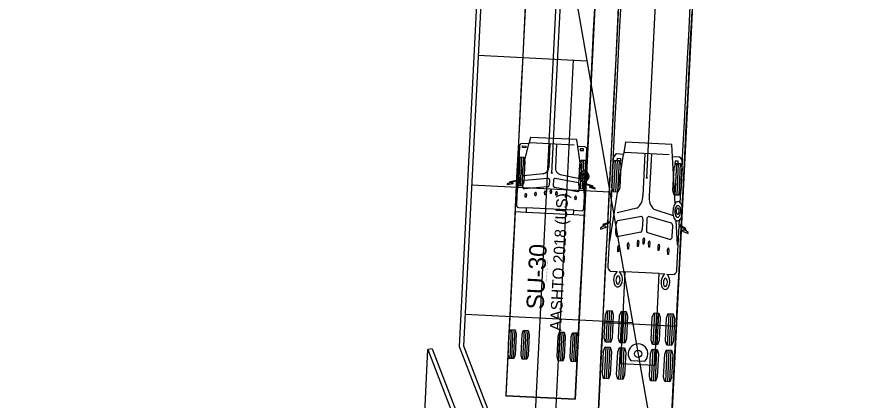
# Model space of a CAD drawing. Extents: x 260275 to 261282, y 610916 to 614143.
# Drawn here: x 260986.2 to 261084.3, y 612110.7 to 612155 of the extents above; entities that cross this region are included whole.
import ezdxf

# ---------------------------------------------------------------- set-up
doc = ezdxf.new("R2010")
doc.units = 0
for name, color, linetype in [('GE_X_Alignment', 7, 'Continuous'), ('PV_P_Curb', 7, 'Continuous'), ('PV_P_EOP', 7, 'Continuous'), ('PV_P_Joint', 7, 'Continuous'), ('TopoDOT_Transients', 7, 'Continuous')]:
    doc.layers.add(name, color=color, linetype=linetype)

msp = doc.modelspace()

# ---------------------------------------------------------------- linework, layer by layer
at = {"layer": 'GE_X_Alignment'}
msp.add_line((260986.249, 610915.954), (261148.276, 614142.838), dxfattribs=at)
at = {"layer": 'PV_P_Curb'}
for p, q in [((261041.82, 612206.041), (261037.345, 612116.921)), ((261034.244, 612116.627), (261033.739, 612116.547)), ((261034.244, 612116.627), (261053.627, 612066.228)), ((261037.345, 612116.921), (261056.48, 612067.167)), ((261034.545, 612115.844), (261053.68, 612066.09))]:
    msp.add_line(p, q, dxfattribs=at)
at = {"layer": 'PV_P_EOP'}
for p, q in [((261042.321, 612206.054), (261037.849, 612116.977)), ((261045.432, 612188.236), (261059.122, 612109.815)), ((261031.212, 612066.209), (261033.739, 612116.547)), ((261033.739, 612116.547), (261053.122, 612066.147)), ((261037.86, 612116.976), (261056.985, 612067.248))]:
    msp.add_line(p, q, dxfattribs=at)
at = {"layer": 'PV_P_Joint'}
for p, q in [((261039.537, 612150.6), (261052.112, 612149.968)), ((261050.523, 612150.048), (261048.266, 612105.105)), ((261038.785, 612135.619), (261054.757, 612134.817)), ((261038.033, 612120.638), (261057.406, 612119.665))]:
    msp.add_line(p, q, dxfattribs=at)
at = {"layer": 'TopoDOT_Transients'}
for p, q in [((261059.045, 612136.423), (261081.046, 612574.591)), ((261048.059, 612136.974), (261068.197, 612538.052)), ((261044.048, 612134.867), (261045.389, 612140.334)), ((261044.677, 612139.913), (261044.687, 612140.107)), ((261044.687, 612140.107), (261045.065, 612140.088)), ((261045.065, 612140.088), (261045.056, 612139.895)), ((261050.643, 612140.193), (261045.544, 612140.449)), ((261047.844, 612140.334), (261047.71, 612137.669)), ((261048.609, 612140.295), (261048.475, 612137.631)), ((261051.47, 612137.084), (261051.052, 612140.05)), ((261061.928, 612140.283), (261056.563, 612140.552)), ((261045.056, 612139.895), (261044.677, 612139.913)), ((261051.349, 612139.773), (261051.339, 612139.579)), ((261051.339, 612139.579), (261051.718, 612139.56)), ((261051.727, 612139.754), (261051.349, 612139.773)), ((261051.718, 612139.56), (261051.727, 612139.754)), ((261051.974, 612137.175), (261052.1, 612139.694)), ((261054.771, 612129.067), (261056.342, 612139.135)), ((261061.602, 612139.096), (261056.503, 612139.352)), ((261058.803, 612139.237), (261058.558, 612134.351)), ((261059.568, 612139.198), (261059.322, 612134.313)), ((261044.355, 612138.829), (261044.188, 612135.5)), ((261044.563, 612138.818), (261044.396, 612135.489)), ((261044.772, 612138.808), (261044.604, 612135.479)), ((261051.513, 612138.469), (261051.346, 612135.14)), ((261051.721, 612138.459), (261051.554, 612135.13)), ((261051.929, 612138.449), (261051.762, 612135.119)), ((261055.371, 612138.443), (261055.187, 612134.781)), ((261055.6, 612138.431), (261055.416, 612134.769)), ((261055.612, 612138.335), (261055.63, 612138.69)), ((261055.99, 612138.316), (261055.612, 612138.335)), ((261055.63, 612138.69), (261056.008, 612138.671)), ((261055.829, 612138.42), (261055.645, 612134.758)), ((261056.008, 612138.671), (261055.99, 612138.316)), ((261062.301, 612133.437), (261062.006, 612138.851)), ((261062.445, 612138.087), (261062.261, 612134.425)), ((261062.292, 612138.356), (261062.274, 612138)), ((261062.67, 612138.337), (261062.292, 612138.356)), ((261062.674, 612138.076), (261062.49, 612134.414)), ((261062.652, 612137.981), (261062.67, 612138.337)), ((261062.903, 612138.064), (261062.719, 612134.402)), ((261062.905, 612133.54), (261063.141, 612138.235)), ((261062.274, 612138), (261062.652, 612137.981)), ((261047.072, 612136.893), (261044.794, 612136.662)), ((261044.9, 612136.163), (261047.609, 612136.379)), ((261047.78, 612136.168), (261047.749, 612135.552)), ((261048.255, 612136.144), (261048.224, 612135.528)), ((261051.12, 612135.851), (261048.447, 612136.337)), ((261049.032, 612136.795), (261051.288, 612136.334)), ((261044.708, 612135.353), (261044.739, 612135.969)), ((261047.588, 612135.358), (261044.879, 612135.142)), ((261048.366, 612135.319), (261051.039, 612134.833)), ((261051.23, 612135.025), (261051.261, 612135.641)), ((261051.838, 612134.475), (261051.622, 612136.009)), ((261044.991, 612134.183), (261044.97, 612134.484)), ((261045.073, 612134.178), (261044.991, 612134.183)), ((261045.124, 612134.476), (261045.073, 612134.178)), ((261046.117, 612134.337), (261046.096, 612134.652)), ((261046.2, 612134.333), (261046.117, 612134.337)), ((261046.251, 612134.644), (261046.2, 612134.333)), ((261047.242, 612134.463), (261047.221, 612134.764)), ((261047.325, 612134.459), (261047.242, 612134.463)), ((261047.376, 612134.756), (261047.325, 612134.459)), ((261047.898, 612134.598), (261047.877, 612134.9)), ((261047.981, 612134.594), (261047.898, 612134.598)), ((261048.031, 612134.892), (261047.981, 612134.594)), ((261048.537, 612134.398), (261048.516, 612134.699)), ((261048.62, 612134.394), (261048.537, 612134.398)), ((261048.67, 612134.691), (261048.62, 612134.394)), ((261049.644, 612134.16), (261049.623, 612134.461)), ((261049.726, 612134.155), (261049.644, 612134.16)), ((261049.777, 612134.453), (261049.726, 612134.155)), ((261050.749, 612133.893), (261050.728, 612134.195)), ((261050.882, 612134.187), (261050.831, 612133.889)), ((261050.831, 612133.889), (261050.749, 612133.893)), ((261050.565, 612132.129), (261045.08, 612132.404)), ((261050.592, 612132.66), (261045.107, 612132.935)), ((261057.886, 612132.904), (261055.593, 612132.385)), ((261059.846, 612132.805), (261062.087, 612132.056)), ((261055.679, 612131.476), (261058.402, 612131.985)), ((261058.565, 612131.606), (261058.508, 612130.477)), ((261059.04, 612131.582), (261058.983, 612130.453)), ((261061.899, 612131.164), (261059.24, 612131.943)), ((261062.561, 612128.675), (261062.408, 612131.475)), ((261053.998, 612130.835), (261053.977, 612130.819)), ((261054.024, 612130.832), (261053.998, 612130.835)), ((261055.452, 612129.985), (261055.509, 612131.114)), ((261061.975, 612129.657), (261062.031, 612130.786)), ((261063.48, 612130.357), (261063.506, 612130.357)), ((261063.506, 612130.357), (261063.526, 612130.339)), ((261058.338, 612130.114), (261055.615, 612129.606)), ((261058.618, 612128.736), (261058.609, 612129.287)), ((261058.764, 612129.279), (261058.7, 612128.732)), ((261059.116, 612130.075), (261061.775, 612129.297)), ((261055.687, 612127.853), (261055.679, 612128.404)), ((261055.833, 612128.396), (261055.769, 612127.849)), ((261056.822, 612128.183), (261056.814, 612128.758)), ((261056.968, 612128.751), (261056.905, 612128.178)), ((261057.955, 612128.46), (261057.946, 612129.011)), ((261058.037, 612128.456), (261057.955, 612128.46)), ((261058.101, 612129.003), (261058.037, 612128.456)), ((261058.7, 612128.732), (261058.618, 612128.736)), ((261059.25, 612128.395), (261059.241, 612128.946)), ((261059.332, 612128.391), (261059.25, 612128.395)), ((261059.395, 612128.938), (261059.332, 612128.391)), ((261060.349, 612128.006), (261060.34, 612128.556)), ((261060.494, 612128.548), (261060.431, 612128.001)), ((261055.769, 612127.849), (261055.687, 612127.853)), ((261056.905, 612128.178), (261056.822, 612128.183)), ((261060.431, 612128.001), (261060.349, 612128.006)), ((261061.445, 612127.564), (261061.437, 612128.115)), ((261061.527, 612127.56), (261061.445, 612127.564)), ((261061.591, 612128.107), (261061.527, 612127.56)), ((261054.848, 612125.619), (261055.622, 612125.581)), ((261060.478, 612125.337), (261056.509, 612125.536)), ((261061.364, 612125.292), (261062.139, 612125.253)), ((261054.498, 612121.065), (261054.314, 612117.402)), ((261054.727, 612121.053), (261054.543, 612117.391)), ((261054.956, 612121.042), (261054.772, 612117.379)), ((261056.146, 612120.982), (261055.962, 612117.32)), ((261056.375, 612120.97), (261056.191, 612117.308)), ((261056.604, 612120.959), (261056.42, 612117.297)), ((261059.925, 612120.792), (261059.741, 612117.13)), ((261060.154, 612120.781), (261059.97, 612117.119)), ((261060.382, 612120.769), (261060.199, 612117.107)), ((261061.573, 612120.709), (261061.389, 612117.047)), ((261061.801, 612120.698), (261061.618, 612117.036)), ((261062.03, 612120.686), (261061.846, 612117.024)), ((261043.352, 612118.854), (261043.185, 612115.525)), ((261043.561, 612118.844), (261043.393, 612115.514)), ((261043.769, 612118.833), (261043.601, 612115.504)), ((261044.851, 612118.779), (261044.683, 612115.45)), ((261045.059, 612118.768), (261044.891, 612115.439)), ((261045.267, 612118.758), (261045.1, 612115.429)), ((261049.012, 612118.57), (261048.845, 612115.241)), ((261049.22, 612118.559), (261049.053, 612115.23)), ((261049.428, 612118.549), (261049.261, 612115.22)), ((261050.51, 612118.495), (261050.343, 612115.165)), ((261050.718, 612118.484), (261050.551, 612115.155)), ((261050.926, 612118.474), (261050.759, 612115.145)), ((261054.288, 612116.87), (261054.104, 612113.208)), ((261054.516, 612116.858), (261054.333, 612113.196)), ((261054.745, 612116.847), (261054.561, 612113.185)), ((261055.935, 612116.787), (261055.752, 612113.125)), ((261056.164, 612116.776), (261055.98, 612113.114)), ((261056.393, 612116.764), (261056.209, 612113.102)), ((261059.714, 612116.597), (261059.53, 612112.935)), ((261059.943, 612116.586), (261059.759, 612112.924)), ((261060.172, 612116.574), (261059.988, 612112.912)), ((261061.362, 612116.515), (261061.178, 612112.853)), ((261061.591, 612116.503), (261061.407, 612112.841)), ((261061.82, 612116.492), (261061.636, 612112.83)), ((261057.175, 612115.293), (261058.789, 612115.212))]:
    msp.add_line(p, q, dxfattribs=at)
for points in [[(261051.548, 612071.863), (261074.206, 612523.277)], [(261082.631, 612521.243), (261060.03, 612071.291)], [(261042.767, 612111.356), (261063.016, 612514.614)], [(261070.923, 612512.551), (261050.75, 612110.806), (261042.76, 612111.207), (261042.767, 612111.356), (261042.767, 612111.356)], [(261043.061, 612117.2), (261043.228, 612120.528), (261043.395, 612123.857), (261043.562, 612127.185), (261043.729, 612130.514), (261043.896, 612133.842), (261044.064, 612137.171), (261044.231, 612140.499), (261044.398, 612143.827), (261044.565, 612147.156), (261044.732, 612150.484), (261044.899, 612153.813), (261045.066, 612157.141)], [(261044.064, 612137.175), (261044.231, 612140.503), (261044.398, 612143.832), (261044.565, 612147.16), (261044.732, 612150.489), (261044.899, 612153.817), (261045.067, 612157.145)], [(261051.051, 612116.799), (261051.218, 612120.127), (261051.385, 612123.456), (261051.552, 612126.784), (261051.719, 612130.112), (261051.886, 612133.441), (261052.054, 612136.769), (261052.221, 612140.098), (261052.388, 612143.426), (261052.555, 612146.755), (261052.722, 612150.083), (261052.889, 612153.412), (261053.056, 612156.74)], [(261052.054, 612136.774), (261052.221, 612140.102), (261052.388, 612143.43), (261052.555, 612146.759), (261052.722, 612150.087), (261052.889, 612153.416), (261053.056, 612156.744)], [(261053.438, 612109.507), (261053.605, 612112.837), (261053.772, 612116.166), (261053.94, 612119.496), (261054.107, 612122.825), (261054.274, 612126.155), (261054.441, 612129.484), (261054.608, 612132.814), (261054.776, 612136.144), (261054.943, 612139.473), (261055.11, 612142.803), (261055.277, 612146.132), (261055.444, 612149.462), (261055.611, 612152.791), (261055.779, 612156.121)], [(261055.05, 612136.623), (261055.217, 612139.953), (261055.384, 612143.282), (261055.551, 612146.612), (261055.719, 612149.941), (261055.886, 612153.271), (261056.053, 612156.6)], [(261063.04, 612136.222), (261063.207, 612139.551), (261063.374, 612142.881), (261063.541, 612146.211), (261063.709, 612149.54), (261063.876, 612152.87), (261064.043, 612156.199)], [(261061.927, 612109.081), (261062.095, 612112.41), (261062.262, 612115.74), (261062.429, 612119.07), (261062.596, 612122.399), (261062.763, 612125.729), (261062.93, 612129.058), (261063.098, 612132.388), (261063.265, 612135.717), (261063.432, 612139.047), (261063.599, 612142.376), (261063.766, 612145.706), (261063.934, 612149.035), (261064.101, 612152.365), (261064.268, 612155.695)], [(261051.862, 612140.009), (261051.056, 612140.05), (261051.051, 612140.054), (261050.942, 612140.832), (261050.9, 612140.837), (261048.259, 612140.969), (261045.619, 612141.102), (261045.577, 612141.102), (261045.39, 612140.339), (261045.385, 612140.334), (261044.578, 612140.375)], [(261044.31, 612140.085), (261044.113, 612136.157), (261044.105, 612136.145), (261043.264, 612135.961), (261043.263, 612135.961)], [(261061.928, 612140.283), (261056.563, 612140.552), (261056.342, 612139.135), (261055.529, 612139.176)], [(261062.819, 612138.81), (261062.006, 612138.851), (261061.928, 612140.271)], [(261055.151, 612138.636), (261054.786, 612131.369), (261054.03, 612131.037)], [(261043.219, 612135.89), (261043.216, 612135.843), (261043.215, 612135.842), (261042.914, 612135.726), (261042.911, 612135.661), (261042.914, 612135.661), (261043.576, 612135.767), (261043.579, 612135.768), (261043.582, 612135.824), (261043.579, 612135.824), (261043.263, 612135.848), (261043.262, 612135.849), (261043.265, 612135.893)], [(261043.277, 612135.913), (261043.278, 612135.913), (261044.105, 612136.091), (261044.109, 612136.079), (261043.97, 612133.308)], [(261051.76, 612132.917), (261051.899, 612135.688), (261051.904, 612135.699), (261052.71, 612135.439), (261052.71, 612135.439)], [(261052.729, 612135.486), (261052.728, 612135.486), (261051.909, 612135.753), (261051.903, 612135.766), (261051.914, 612135.993)], [(261052.72, 612135.418), (261052.718, 612135.374), (261052.718, 612135.374), (261052.401, 612135.381), (261052.398, 612135.381), (261052.395, 612135.325), (261052.398, 612135.324), (261053.046, 612135.152), (261053.049, 612135.152), (261053.052, 612135.217), (261052.764, 612135.363), (261052.764, 612135.363), (261052.766, 612135.411)], [(261044.208, 612132.98), (261045.103, 612132.935), (261045.106, 612132.932), (261045.08, 612132.405), (261045.069, 612132.405), (261043.827, 612132.467), (261042.76, 612111.207), (261046.755, 612111.007), (261050.75, 612110.806), (261051.817, 612132.066), (261050.576, 612132.128), (261050.565, 612132.13), (261050.591, 612132.656), (261050.595, 612132.66), (261051.49, 612132.615)], [(261054.042, 612130.95), (261054.042, 612130.95), (261054.781, 612131.269), (261054.526, 612126.194)], [(261063.496, 612130.562), (261062.776, 612130.967), (261062.805, 612131.54)], [(261053.982, 612130.906), (261053.977, 612130.819), (261053.67, 612130.593), (261053.664, 612130.473), (261054.338, 612130.697), (261054.343, 612130.8), (261054.024, 612130.832), (261054.029, 612130.914)], [(261062.516, 612125.793), (261062.771, 612130.868), (261063.474, 612130.477), (261063.475, 612130.476)], [(261063.484, 612130.439), (261063.48, 612130.357), (261063.16, 612130.357), (261063.154, 612130.254), (261063.802, 612129.964), (261063.809, 612130.084), (261063.526, 612130.339), (261063.53, 612130.427)], [(261055.879, 612125.568), (261056.509, 612125.536), (261055.977, 612114.949), (261059.946, 612114.75), (261060.478, 612125.337), (261061.107, 612125.305)], [(261060.011, 612071.363), (261060.033, 612071.362), (261062.437, 612119.231), (261058.192, 612119.444), (261053.948, 612119.657), (261051.544, 612071.788), (261051.567, 612071.787)]]:
    msp.add_lwpolyline(points, dxfattribs=at)
for points in [[(261044.304, 612138.831), (261044.823, 612138.805), (261044.956, 612138.331), (261044.836, 612135.934), (261044.656, 612135.476), (261044.137, 612135.502), (261044.004, 612135.976), (261044.124, 612138.373)], [(261051.461, 612138.472), (261051.981, 612138.446), (261052.114, 612137.972), (261051.994, 612135.575), (261051.814, 612135.117), (261051.294, 612135.143), (261051.161, 612135.617), (261051.282, 612138.014)], [(261055.314, 612138.445), (261055.885, 612138.417), (261056.032, 612137.895), (261055.899, 612135.259), (261055.701, 612134.755), (261055.13, 612134.783), (261054.984, 612135.305), (261055.116, 612137.941)], [(261062.388, 612138.09), (261062.96, 612138.062), (261063.106, 612137.54), (261062.974, 612134.904), (261062.776, 612134.4), (261062.205, 612134.428), (261062.058, 612134.95), (261062.191, 612137.586)], [(261054.441, 612121.067), (261055.013, 612121.039), (261055.159, 612120.517), (261055.027, 612117.881), (261054.829, 612117.377), (261054.258, 612117.405), (261054.111, 612117.927), (261054.244, 612120.563)], [(261056.089, 612120.985), (261056.661, 612120.956), (261056.807, 612120.435), (261056.675, 612117.798), (261056.477, 612117.294), (261055.905, 612117.323), (261055.759, 612117.844), (261055.891, 612120.481)], [(261059.868, 612120.795), (261060.439, 612120.766), (261060.586, 612120.245), (261060.453, 612117.608), (261060.255, 612117.104), (261059.684, 612117.133), (261059.538, 612117.654), (261059.67, 612120.291)], [(261061.516, 612120.712), (261062.087, 612120.683), (261062.233, 612120.162), (261062.101, 612117.525), (261061.903, 612117.021), (261061.332, 612117.05), (261061.186, 612117.571), (261061.318, 612120.208)], [(261043.301, 612118.857), (261043.82, 612118.831), (261043.953, 612118.357), (261043.833, 612115.96), (261043.653, 612115.501), (261043.134, 612115.527), (261043.001, 612116.001), (261043.121, 612118.398)], [(261044.799, 612118.781), (261045.318, 612118.755), (261045.451, 612118.281), (261045.331, 612115.884), (261045.151, 612115.426), (261044.632, 612115.452), (261044.499, 612115.926), (261044.619, 612118.323)], [(261048.96, 612118.572), (261049.48, 612118.546), (261049.613, 612118.072), (261049.492, 612115.675), (261049.313, 612115.217), (261048.793, 612115.243), (261048.66, 612115.717), (261048.781, 612118.114)], [(261050.459, 612118.497), (261050.978, 612118.471), (261051.111, 612117.997), (261050.991, 612115.6), (261050.811, 612115.142), (261050.291, 612115.168), (261050.158, 612115.642), (261050.279, 612118.039)], [(261054.231, 612116.873), (261054.802, 612116.844), (261054.948, 612116.323), (261054.816, 612113.686), (261054.618, 612113.182), (261054.047, 612113.211), (261053.901, 612113.732), (261054.033, 612116.369)], [(261055.879, 612116.79), (261056.45, 612116.761), (261056.596, 612116.24), (261056.464, 612113.603), (261056.266, 612113.099), (261055.695, 612113.128), (261055.548, 612113.649), (261055.681, 612116.286)], [(261059.657, 612116.6), (261060.229, 612116.571), (261060.375, 612116.05), (261060.243, 612113.413), (261060.045, 612112.909), (261059.473, 612112.938), (261059.327, 612113.459), (261059.459, 612116.096)], [(261061.305, 612116.517), (261061.876, 612116.489), (261062.023, 612115.967), (261061.89, 612113.331), (261061.693, 612112.827), (261061.121, 612112.855), (261060.975, 612113.377), (261061.107, 612116.013)]]:
    msp.add_lwpolyline(points, close=True, dxfattribs=at)
for centre, radius in [((261044.064, 612137.175), 0.0417), ((261048.059, 612136.974), 0.0417), ((261051.799, 612136.591), 0.374), ((261051.799, 612136.591), 0.193), ((261052.054, 612136.774), 0.0417), ((261055.05, 612136.623), 0.0417), ((261059.045, 612136.423), 0.0417), ((261063.04, 612136.222), 0.0417), ((261043.061, 612117.2), 0.0417), ((261051.051, 612116.799), 0.0417), ((261058.022, 612116.06), 0.424)]:
    msp.add_circle(centre, radius, dxfattribs=at)
for centre, radius, start, end in [((261044.592, 612140.093), 0.282, 92.67391, 181.75333), ((261051.821, 612139.73), 0.282, 352.49767, 81.5771), ((261055.93, 612138.493), 0.792, 120.43659, 169.59206), ((261062.352, 612138.171), 0.792, 4.65895, 53.81442), ((261046.938, 612137.654), 0.773, 280.01597, 1.10013), ((261049.242, 612137.539), 0.773, 173.15088, 254.23504), ((261051.868, 612136.596), 0.629, 129.17109, 177.86038), ((261051.803, 612136.677), 0.526, 71.07067, 129.31667), ((261051.732, 612136.595), 0.628, 286.8788, 67.3705), ((261044.931, 612135.973), 0.193, 99.26792, 181.18241), ((261047.598, 612136.195), 0.184, 351.66723, 86.52737), ((261048.439, 612136.153), 0.184, 87.72364, 182.58377), ((261051.868, 612136.581), 0.63, 176.4803, 228.88311), ((261051.795, 612136.504), 0.524, 229.38452, 283.18459), ((261043.242, 612135.925), 0.0418, 59.61742, 236.63235), ((261043.236, 612135.925), 0.0434, 312.53921, 343.21198), ((261044.89, 612135.326), 0.184, 171.66167, 266.53293), ((261047.557, 612135.548), 0.193, 279.26299, 1.18734), ((261048.415, 612135.505), 0.193, 173.06366, 254.98801), ((261051.07, 612135.665), 0.193, 353.06859, 74.98308), ((261052.753, 612135.447), 0.0434, 191.03902, 221.7118), ((261052.747, 612135.448), 0.0418, 297.61865, 114.63358), ((261045.06, 612134.498), 0.091, 94.64508, 188.80895), ((261045.036, 612134.499), 0.0909, 345.40639, 79.64159), ((261046.186, 612134.652), 0.091, 94.64508, 188.80895), ((261046.163, 612134.653), 0.0909, 345.40639, 79.64159), ((261047.311, 612134.778), 0.091, 94.64508, 188.80895), ((261047.288, 612134.779), 0.0909, 345.40639, 79.64159), ((261047.967, 612134.913), 0.091, 94.64508, 188.80895), ((261047.943, 612134.915), 0.091, 345.44206, 79.60593), ((261048.606, 612134.713), 0.0909, 94.60942, 188.84462), ((261048.582, 612134.714), 0.091, 345.44206, 79.60593), ((261049.713, 612134.475), 0.0909, 94.60942, 188.84462), ((261049.689, 612134.476), 0.091, 345.44206, 79.60593), ((261050.818, 612134.209), 0.0909, 94.60942, 188.84462), ((261050.794, 612134.21), 0.091, 345.44206, 79.60593), ((261051.046, 612135.017), 0.184, 267.71808, 2.58934), ((261056.932, 612134.227), 1.631, 305.80134, 4.39207), ((261060.928, 612134.026), 1.631, 169.85894, 228.44967), ((261044.292, 612133.292), 0.323, 177.1255, 254.97391), ((261063.179, 612132.818), 1.074, 138.58211, 162.85096), ((261062.669, 612133.289), 0.38, 90.45588, 140.97941), ((261062.655, 612132.966), 0.268, 92.19814, 155.87577), ((261062.513, 612132.848), 0.407, 8.35614, 71.16055), ((261062.644, 612133.342), 0.328, 37.21385, 86.11819), ((261062.388, 612133.042), 0.719, 15.6559, 43.91288), ((261061.44, 612132.681), 1.731, 3.5106, 18.70836), ((261051.438, 612132.933), 0.323, 279.2771, 357.1255), ((261064.058, 612132.463), 2.012, 176.76687, 195.44978), ((261064.097, 612132.485), 2.049, 161.50654, 177.43184), ((261063.177, 612132.47), 0.914, 173.95993, 216.01791), ((261063.365, 612132.533), 1.098, 150.39127, 178.28386), ((261063.049, 612132.528), 0.617, 169.4131, 202.60389), ((261062.712, 612132.646), 0.27, 108.27444, 181.01824), ((261062.597, 612132.316), 0.12, 192.10162, 337.57965), ((261062.552, 612132.695), 0.22, 8.13535, 69.83363), ((261062.156, 612132.577), 0.631, 330.93378, 13.73431), ((261062.039, 612132.52), 0.913, 320.43513, 0.69541), ((261061.72, 612132.601), 1.234, 356.75519, 14.33734), ((261060.969, 612132.634), 2.204, 344.32456, 3.95974), ((261055.911, 612131.146), 0.403, 125.12521, 184.58316), ((261058.231, 612131.693), 0.342, 348.72731, 58.65379), ((261059.381, 612131.635), 0.342, 115.59721, 185.52369), ((261062.898, 612132.106), 0.799, 192.92493, 232.19257), ((261062.57, 612131.728), 0.301, 237.35677, 321.25506), ((261062.588, 612132.062), 0.199, 220.92879, 321.5681), ((261062.186, 612132.226), 0.924, 312.02262, 348.30076), ((261054.093, 612130.968), 0.127, 145.02093, 209.23008), ((261054.008, 612131.026), 0.0244, 27.99309, 141.30746), ((261053.933, 612130.969), 0.11, 330.07302, 350.18134), ((261058.111, 612130.44), 0.397, 304.88665, 3.04966), ((261059.375, 612130.377), 0.397, 171.20134, 229.36435), ((261061.635, 612130.859), 0.403, 349.66784, 49.12579), ((261063.584, 612130.484), 0.11, 184.06966, 204.17798), ((261063.516, 612130.548), 0.0244, 32.94354, 146.25791), ((261063.425, 612130.5), 0.127, 325.02093, 29.23008), ((261055.777, 612129.897), 0.334, 168.26267, 240.86063), ((261058.799, 612129.319), 0.192, 122.20119, 189.67576), ((261058.578, 612129.33), 0.192, 344.57524, 52.04981), ((261061.642, 612129.603), 0.334, 293.39037, 5.98833), ((261055.868, 612128.436), 0.192, 122.20119, 189.67576), ((261055.648, 612128.448), 0.192, 344.5479, 52.07716), ((261057.003, 612128.766), 0.192, 122.20119, 189.67576), ((261056.783, 612128.777), 0.192, 344.5479, 52.07716), ((261058.136, 612129.043), 0.192, 122.20119, 189.67576), ((261057.915, 612129.055), 0.192, 344.5479, 52.07716), ((261059.431, 612128.978), 0.192, 122.17384, 189.70311), ((261059.21, 612128.989), 0.192, 344.57524, 52.04981), ((261060.53, 612128.589), 0.192, 122.17384, 189.70311), ((261060.309, 612128.6), 0.192, 344.57524, 52.04981), ((261061.626, 612128.147), 0.192, 122.17384, 189.70311), ((261061.406, 612128.158), 0.192, 344.57524, 52.04981), ((261055.094, 612126.135), 0.571, 174.04089, 244.43248), ((261056.541, 612124.6), 1.344, 133.16094, 206.71574), ((261054.867, 612124.685), 1.344, 327.53526, 41.09006), ((261061.945, 612125.791), 0.571, 289.81853, 0.21012), ((261056.326, 612124.571), 0.86, 158.69148, 198.66086), ((261055.799, 612124.789), 0.29, 104.76976, 160.92979), ((261055.663, 612124.83), 0.247, 5.52911, 75.4082), ((261055.058, 612124.633), 0.879, 339.9934, 14.58864), ((261062.026, 612124.325), 1.344, 133.16094, 206.71574), ((261061.83, 612124.293), 0.879, 159.66236, 194.25761), ((261061.248, 612124.55), 0.247, 98.8428, 168.7219), ((261061.109, 612124.522), 0.29, 13.32121, 69.48124), ((261060.563, 612124.359), 0.86, 335.59014, 15.55953), ((261060.352, 612124.409), 1.344, 327.53526, 41.09006), ((261055.681, 612124.182), 0.387, 208.62104, 325.62996), ((261055.732, 612124.353), 0.228, 194.4278, 256.32264), ((261055.629, 612124.389), 0.262, 280.91747, 347.44267), ((261061.165, 612123.898), 0.383, 207.59628, 326.65472), ((261061.238, 612124.107), 0.262, 186.80834, 253.33353), ((261061.132, 612124.082), 0.228, 277.92836, 339.8232), ((261058.022, 612116.06), 1.143, 312.1255, 222.1255)]:
    msp.add_arc(centre, radius, start, end, dxfattribs=at)
for centre, major_axis, start_param, end_param in [((261054.005, 612130.973), (-0.0039, -0.0781), 5.756759, 7.026061), ((261054.005, 612130.973), (0.0039, 0.0781), 4.442794, 5.713538), ((261063.513, 612130.495), (-0.0039, -0.0781), 3.71124, 4.981984), ((261063.513, 612130.495), (0.0039, 0.0781), 2.398717, 3.668019)]:
    msp.add_ellipse(centre, major_axis=major_axis, ratio=0.5, start_param=start_param, end_param=end_param, dxfattribs=at)

# ---------------------------------------------------------------- texts
for s, height, p in [('AASHTO 2018 (US)', 1.33333, (261049.149, 612118.682)), ('SU-30', 2, (261047.104, 612121.145)), ('(c) 2023 Transoft Solutions, Inc. All rights reserved.', 0.08, (261047.465, 612124.35))]:
    msp.add_text(s, height=height, rotation=87.1255, dxfattribs=at).set_placement(p)

doc.saveas('drawing.dxf')
